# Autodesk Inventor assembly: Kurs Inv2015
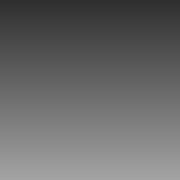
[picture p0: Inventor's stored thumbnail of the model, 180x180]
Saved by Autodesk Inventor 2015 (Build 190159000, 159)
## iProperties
Created: 2010-03
Part Number: Kurs Inv2015
Document SubType Name: Assembly
Designer: Johan Wedeen
Manufacturer: Standard
Standards Organization: Custom
Author: Johan Wedeen
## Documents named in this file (1)
- C:\Users\Public\Documents\Autodesk\Inventor 2015\Templates\InventorKurs\Kurs Inv2015.iam
